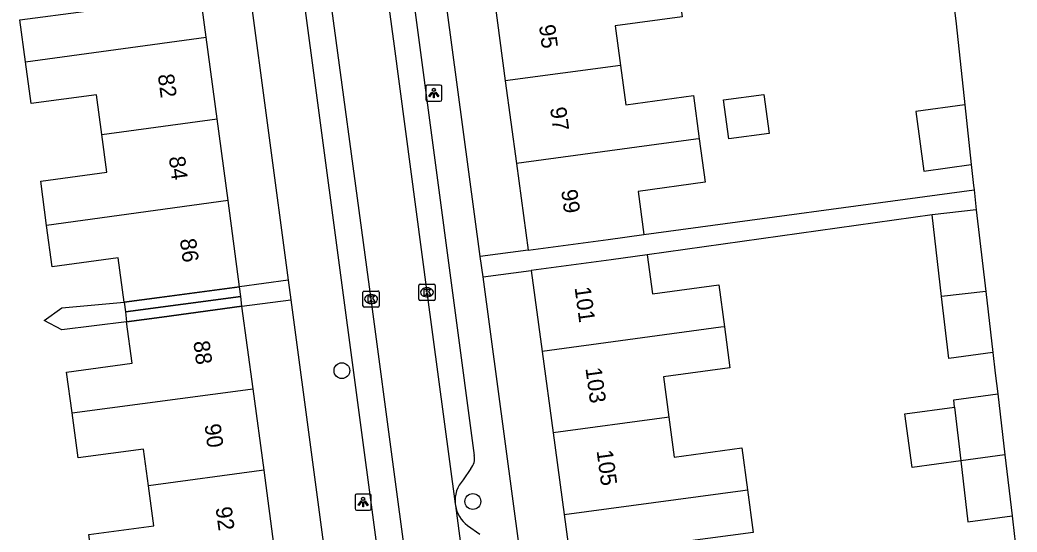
# Model space of a CAD drawing. Extents: x 163150 to 163546, y 380933 to 381635.
# Drawn here: x 163476.8 to 163538.6, y 381207 to 381238.7 of the extents above; entities that cross this region are included whole.
import ezdxf

# ---------------------------------------------------------------- set-up
doc = ezdxf.new("R2010")
doc.units = 0
for name, color, linetype in [('IMGEO_Boom', 7, 'Continuous'), ('IMGEO_Kolk', 7, 'Continuous'), ('IMGEO_Lichtpunt', 7, 'Continuous'), ('IMGEO_Pand', 7, 'Continuous'), ('IMGEO_Pand_nummerreeks', 7, 'Continuous'), ('IMGEO_Pand_overbouw', 7, 'Continuous'), ('IMGEO_Rijbaan_lokaal_open', 7, 'Continuous'), ('IMGEO_Voetpad_open', 7, 'Continuous')]:
    doc.layers.add(name, color=color, linetype=linetype)

msp = doc.modelspace()

# ---------------------------------------------------------------- linework, layer by layer
at = {"layer": 'IMGEO_Boom'}
for centre in [(163496.767, 381217.023), (163504.87, 381208.925)]:
    msp.add_circle(centre, 0.489, dxfattribs=at)
at = {"layer": 'IMGEO_Kolk'}
for p, q in [((163501.532, 381221.448), (163501.532, 381222.3)), ((163501.607, 381222.374), (163502.459, 381222.374)), ((163502.533, 381222.3), (163502.533, 381221.448)), ((163498.071, 381221.028), (163498.071, 381221.88)), ((163498.146, 381221.954), (163498.998, 381221.954)), ((163498.559, 381221.734), (163498.584, 381221.734)), ((163499.072, 381221.88), (163499.072, 381221.028)), ((163502.02, 381222.154), (163502.045, 381222.154)), ((163498.582, 381221.174), (163498.557, 381221.174)), ((163502.459, 381221.374), (163501.607, 381221.374)), ((163502.043, 381221.594), (163502.018, 381221.594)), ((163498.998, 381220.954), (163498.146, 381220.954))]:
    msp.add_line(p, q, dxfattribs=at)
for points in [[(163501.532, 381221.448), (163501.532, 381222.3)], [(163501.607, 381222.374), (163502.459, 381222.374)], [(163502.533, 381222.3), (163502.533, 381221.448)], [(163498.071, 381221.028), (163498.071, 381221.88)], [(163498.146, 381221.954), (163498.998, 381221.954)], [(163498.392, 381221.654), (163498.515, 381221.654), (163498.515, 381221.503), (163498.645, 381221.654), (163498.809, 381221.654), (163498.663, 381221.503), (163498.816, 381221.254), (163498.664, 381221.254), (163498.579, 381221.418), (163498.515, 381221.351), (163498.515, 381221.254), (163498.392, 381221.254), (163498.392, 381221.654)], [(163499.072, 381221.88), (163499.072, 381221.028)], [(163501.853, 381222.074), (163501.976, 381222.074), (163501.976, 381221.923), (163502.106, 381222.074), (163502.27, 381222.074), (163502.124, 381221.923), (163502.277, 381221.674), (163502.125, 381221.674), (163502.04, 381221.838), (163501.976, 381221.771), (163501.976, 381221.674), (163501.853, 381221.674), (163501.853, 381222.074)], [(163502.459, 381221.374), (163501.607, 381221.374)], [(163498.998, 381220.954), (163498.146, 381220.954)]]:
    msp.add_lwpolyline(points, dxfattribs=at)
for centre, start, end in [((163501.609, 381222.298), 91.55205, 178.44795), ((163501.609, 381222.298), 91.55205, 178.44795), ((163502.457, 381222.298), 1.55205, 88.44795), ((163502.457, 381222.298), 1.55205, 88.44795), ((163498.148, 381221.878), 91.55205, 178.44795), ((163498.148, 381221.878), 91.55205, 178.44795), ((163498.996, 381221.878), 1.55205, 88.44795), ((163498.996, 381221.878), 1.55205, 88.44795), ((163498.148, 381221.03), 181.55205, 268.44795), ((163498.148, 381221.03), 181.55205, 268.44795), ((163498.996, 381221.03), 271.55205, 358.44795), ((163498.996, 381221.03), 271.55205, 358.44795), ((163501.609, 381221.45), 181.55205, 268.44795), ((163501.609, 381221.45), 181.55205, 268.44795), ((163502.457, 381221.45), 271.55205, 358.44795), ((163502.457, 381221.45), 271.55205, 358.44795)]:
    msp.add_arc(centre, 0.0765, start, end, dxfattribs=at)
for centre, major_axis, ratio, start_param, end_param in [((163498.558, 381221.454), (-0.387, 0.002), 0.722429, 4.712389, 7.853982), ((163498.583, 381221.454), (-0.39, 0.002), 0.717154, 1.570796, 4.712389), ((163502.019, 381221.874), (-0.387, 0.002), 0.722429, 4.712389, 7.853982), ((163502.044, 381221.874), (-0.39, 0.002), 0.717154, 1.570796, 4.712389)]:
    msp.add_ellipse(centre, major_axis=major_axis, ratio=ratio, start_param=start_param, end_param=end_param, dxfattribs=at)
at = {"layer": 'IMGEO_Lichtpunt'}
for p, q in [((163501.957, 381234.608), (163501.957, 381233.801)), ((163501.957, 381234.608), (163501.957, 381233.801)), ((163502.859, 381234.703), (163502.051, 381234.703)), ((163502.859, 381234.703), (163502.051, 381234.703)), ((163502.953, 381233.801), (163502.953, 381234.608)), ((163502.953, 381233.801), (163502.953, 381234.608)), ((163502.051, 381233.707), (163502.859, 381233.707)), ((163502.051, 381233.707), (163502.859, 381233.707)), ((163497.58, 381209.292), (163497.58, 381208.485)), ((163497.58, 381209.292), (163497.58, 381208.485)), ((163498.482, 381209.387), (163497.674, 381209.387)), ((163498.482, 381209.387), (163497.674, 381209.387)), ((163498.576, 381208.485), (163498.576, 381209.292)), ((163498.576, 381208.485), (163498.576, 381209.292)), ((163497.674, 381208.391), (163498.482, 381208.391)), ((163497.674, 381208.391), (163498.482, 381208.391))]:
    msp.add_line(p, q, dxfattribs=at)
for points in [[(163502.331, 381234.272), (163502.37, 381234.244), (163502.182, 381233.982), (163502.144, 381234.009), (163502.331, 381234.272)], [(163502.433, 381234.224), (163502.48, 381234.224), (163502.48, 381233.902), (163502.433, 381233.902), (163502.433, 381234.224)], [(163502.543, 381234.244), (163502.581, 381234.271), (163502.768, 381234.009), (163502.729, 381233.981), (163502.543, 381234.244)], [(163497.954, 381208.956), (163497.993, 381208.928), (163497.805, 381208.666), (163497.767, 381208.693), (163497.954, 381208.956)], [(163498.056, 381208.908), (163498.103, 381208.908), (163498.103, 381208.586), (163498.056, 381208.586), (163498.056, 381208.908)], [(163498.166, 381208.928), (163498.204, 381208.955), (163498.391, 381208.693), (163498.352, 381208.665), (163498.166, 381208.928)]]:
    msp.add_lwpolyline(points, dxfattribs=at)
for centre in [(163502.456, 381234.406), (163498.079, 381209.09)]:
    msp.add_circle(centre, 0.0994, dxfattribs=at)
for centre, start, end in [((163502.051, 381234.608), 90, 180), ((163502.051, 381234.608), 90, 180), ((163502.859, 381234.608), 0, 90), ((163502.859, 381234.608), 0, 90), ((163502.051, 381233.801), 180, 270), ((163502.051, 381233.801), 180, 270), ((163502.859, 381233.801), 270, 0), ((163502.859, 381233.801), 270, 360), ((163497.674, 381209.292), 90, 180), ((163497.674, 381209.292), 90, 180), ((163498.482, 381209.292), 0, 90), ((163498.482, 381209.292), 0, 90), ((163497.674, 381208.485), 180, 270), ((163497.674, 381208.485), 180, 270), ((163498.482, 381208.485), 270, 0), ((163498.482, 381208.485), 270, 360)]:
    msp.add_arc(centre, 0.0946, start, end, dxfattribs=at)
at = {"layer": 'IMGEO_Pand'}
for points in [[(163488.363, 381237.675), (163487.685, 381242.734)], [(163477.186, 381236.14), (163476.838, 381238.737), (163480.93, 381239.286), (163480.598, 381241.761)], [(163517.488, 381241.478), (163517.83, 381238.933), (163513.69, 381238.376), (163514.021, 381235.914)], [(163506.207, 381239.968), (163506.881, 381234.959)], [(163477.186, 381236.14), (163488.363, 381237.675)], [(163489.042, 381232.616), (163488.363, 381237.675)], [(163481.908, 381231.637), (163481.578, 381234.1), (163477.532, 381233.557), (163477.186, 381236.14)], [(163514.021, 381235.914), (163506.881, 381234.959)], [(163514.021, 381235.914), (163514.348, 381233.488), (163518.529, 381234.05), (163518.889, 381231.376)], [(163506.881, 381234.959), (163507.569, 381229.843)], [(163522.877, 381234.128), (163523.205, 381231.707), (163520.713, 381231.37), (163520.386, 381233.791), (163522.877, 381234.128)], [(163535.323, 381233.486), (163532.287, 381233.072), (163532.791, 381229.37), (163535.722, 381229.776)], [(163535.323, 381233.486), (163535.722, 381229.776)], [(163481.908, 381231.637), (163489.042, 381232.616)], [(163489.721, 381227.557), (163489.042, 381232.616)], [(163478.489, 381226.015), (163478.122, 381228.752), (163482.221, 381229.302), (163481.908, 381231.637)], [(163518.889, 381231.376), (163518.668, 381231.346), (163507.569, 381229.843)], [(163518.889, 381231.376), (163519.251, 381228.682), (163515.098, 381228.123), (163515.459, 381225.442)], [(163507.569, 381229.843), (163508.291, 381224.478)], [(163489.721, 381227.557), (163478.489, 381226.015)], [(163490.437, 381222.219), (163489.721, 381227.557)], [(163536.023, 381226.978), (163533.3, 381226.66)], [(163533.89, 381221.604), (163533.3, 381226.66)], [(163536.023, 381226.978), (163536.618, 381221.927)], [(163483.286, 381221.26), (163482.919, 381223.997), (163478.833, 381223.448), (163478.489, 381226.015)], [(163508.291, 381224.478), (163513.247, 381225.145), (163515.459, 381225.442)], [(163515.663, 381224.189), (163513.437, 381223.889), (163508.481, 381223.221)], [(163515.663, 381224.189), (163515.989, 381221.775), (163520.096, 381222.329), (163520.445, 381219.741)], [(163508.481, 381223.221), (163509.156, 381218.215)], [(163483.286, 381221.26), (163485.482, 381221.555), (163490.437, 381222.219)], [(163536.618, 381221.927), (163533.89, 381221.604)], [(163537.063, 381218.145), (163534.336, 381217.777), (163533.89, 381221.604)], [(163536.618, 381221.927), (163537.063, 381218.145)], [(163490.583, 381221.009), (163485.628, 381220.344), (163483.444, 381220.051)], [(163491.268, 381215.906), (163490.583, 381221.009)], [(163480.065, 381214.406), (163479.726, 381216.934), (163483.789, 381217.479), (163483.444, 381220.051)], [(163520.445, 381219.741), (163520.224, 381219.711), (163509.156, 381218.215)], [(163520.445, 381219.741), (163520.789, 381217.19), (163516.668, 381216.634), (163517.005, 381214.135)], [(163509.156, 381218.215), (163509.837, 381213.166)], [(163480.065, 381214.406), (163491.119, 381215.886), (163491.268, 381215.906)], [(163491.945, 381210.854), (163491.268, 381215.906)], [(163534.686, 381214.77), (163534.635, 381215.209), (163537.365, 381215.579)], [(163537.365, 381215.579), (163537.809, 381211.805)], [(163484.795, 381209.897), (163484.489, 381212.173), (163480.437, 381211.63), (163480.065, 381214.406)], [(163535.075, 381211.436), (163532.062, 381211.028), (163531.612, 381214.354), (163534.686, 381214.77)], [(163534.686, 381214.77), (163535.075, 381211.436)], [(163517.005, 381214.135), (163516.87, 381214.117), (163509.837, 381213.166)], [(163517.005, 381214.135), (163517.337, 381211.678), (163521.516, 381212.241), (163521.865, 381209.651)], [(163509.837, 381213.166), (163510.518, 381208.118)], [(163537.809, 381211.805), (163535.075, 381211.436)], [(163537.809, 381211.805), (163538.252, 381208.042)], [(163535.075, 381211.436), (163535.514, 381207.671), (163538.252, 381208.042)], [(163491.945, 381210.854), (163491.794, 381210.834), (163484.795, 381209.897)], [(163492.623, 381205.804), (163491.945, 381210.854)], [(163481.454, 381204.308), (163481.11, 381206.874), (163485.128, 381207.413), (163484.795, 381209.897)], [(163510.518, 381208.118), (163521.575, 381209.612), (163521.865, 381209.651)], [(163521.865, 381209.651), (163522.222, 381207.008), (163518.021, 381206.442), (163518.346, 381204.034)], [(163510.518, 381208.118), (163511.199, 381203.067)]]:
    msp.add_lwpolyline(points, dxfattribs=at)
at = {"layer": 'IMGEO_Pand_overbouw'}
for points in [[(163483.286, 381221.26), (163483.365, 381220.656), (163490.51, 381221.614), (163490.437, 381222.219), (163485.482, 381221.555)], [(163490.583, 381221.009), (163490.51, 381221.614), (163483.365, 381220.656), (163483.444, 381220.051), (163485.628, 381220.344)]]:
    msp.add_lwpolyline(points, close=True, dxfattribs=at)
at = {"layer": 'IMGEO_Rijbaan_lokaal_open'}
for points in [[(163498.069, 381251.55), (163498.277, 381250), (163499.186, 381243.223), (163500, 381237.114), (163502.031, 381221.873), (163503.782, 381208.782)], [(163503.549, 381184.23), (163501.36, 381200.568), (163500, 381210.764), (163498.574, 381221.455), (163495.662, 381242.977), (163494.749, 381250), (163494.609, 381251.077)], [(163534.624, 381239.844), (163534.783, 381238.501), (163535.323, 381233.486)], [(163535.722, 381229.776), (163535.86, 381228.491), (163535.898, 381228.212)], [(163535.898, 381228.212), (163536.023, 381226.978)], [(163537.063, 381218.145), (163537.213, 381216.868), (163537.365, 381215.579)], [(163503.782, 381208.782), (163503.796, 381208.674)], [(163503.796, 381208.674), (163504.806, 381200.993), (163506.998, 381184.771)], [(163538.252, 381208.042), (163538.404, 381206.748), (163538.558, 381205.441)]]:
    msp.add_lwpolyline(points, dxfattribs=at)
at = {"layer": 'IMGEO_Voetpad_open'}
for points in [[(163492.278, 381306.923), (163499.864, 381250), (163500, 381248.982), (163504.96, 381211.766)], [(163488.802, 381281.887), (163493.061, 381250), (163500, 381198.044), (163501.78, 381184.716), (163502.086, 381184.001), (163503.191, 381183.057), (163503.412, 381182.858)], [(163505.332, 381224.08), (163501.849, 381250), (163501.219, 381254.688)], [(163489.37, 381253.175), (163489.793, 381250), (163493.444, 381222.62)], [(163515.459, 381225.442), (163535.898, 381228.212)], [(163533.3, 381226.66), (163515.663, 381224.189)], [(163508.291, 381224.478), (163505.332, 381224.08)], [(163505.501, 381222.821), (163505.332, 381224.08)], [(163505.501, 381222.821), (163508.481, 381223.221)], [(163493.444, 381222.62), (163490.437, 381222.219)], [(163493.444, 381222.62), (163493.605, 381221.412)], [(163509.584, 381192.438), (163505.501, 381222.821)], [(163483.444, 381220.051), (163479.421, 381219.56), (163478.338, 381220.119), (163479.43, 381220.912), (163483.286, 381221.26)], [(163490.583, 381221.009), (163493.605, 381221.412)], [(163493.605, 381221.412), (163497.667, 381190.955)], [(163504.75, 381210.967), (163504.267, 381210.268)], [(163504.539, 381207.441), (163505.299, 381206.898)]]:
    msp.add_lwpolyline(points, dxfattribs=at)
for centre, radius, start, end in [((163504.107, 381211.563), 0.876, 317.15344, 13.39473), ((163505.7, 381208.978), 1.928, 138.00538, 185.84337), ((163505.701, 381208.982), 1.93, 189.17345, 232.97248)]:
    msp.add_arc(centre, radius, start, end, dxfattribs=at)

# ---------------------------------------------------------------- texts
at = {"layer": 'IMGEO_Pand_nummerreeks'}
for s, rotation, p in [('95', 277.66097, (163508.963, 381238.386)), ('82', 277.64144, (163485.368, 381235.334)), ('97', 277.66097, (163509.649, 381233.284)), ('84', 277.64144, (163486.051, 381230.239)), ('99', 277.66097, (163510.335, 381228.183)), ('86', 277.64144, (163486.734, 381225.147)), ('101', 277.68018, (163511.167, 381222.165)), ('88', 277.64123, (163487.568, 381218.817)), ('103', 277.68018, (163511.84, 381217.168)), ('90', 277.64123, (163488.258, 381213.676)), ('105', 277.68018, (163512.529, 381212.057)), ('92', 277.64123, (163488.946, 381208.54))]:
    msp.add_text(s, height=1, rotation=rotation, dxfattribs=at).set_placement(p)

doc.saveas('drawing.dxf')
